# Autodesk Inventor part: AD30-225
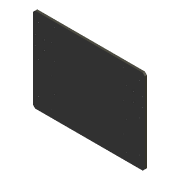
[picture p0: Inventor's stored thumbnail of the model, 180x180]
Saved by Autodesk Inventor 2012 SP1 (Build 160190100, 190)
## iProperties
Shininess: 0.0
Created: 2000-06
Part Number: AD30-225
Project: BONDING PRESS
Description: BASEPLATE, PRESS
Document SubType Name: Modeling
Designer: Ron
Material: Aluminum-6061
Density: 2.71 g/cm^3
Density: 0.0
Volumn: 0.0
Area: 0.0
PropertySet Name: Model Information
Control State: 0
Master: False
Checked Out: False
Title: BASEPLATE, PRESS
Author: Ron
Revision Number: A
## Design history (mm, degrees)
node "Extrusion1" dims "d2" = 12.7, "d3" = 0
  sketch "Sketch1"
    geometry: L1 (-330, 250)-(330, 250); L2 (330, 250)-(330, -250); L3 (330, -250)-(-330, -250); L4 (-330, -250)-(-330, 250); L5 (330, -250)-(-330, 250); 2 further points
    constraints: 10 end point, 2 parallel, 1 coincident, 1 horizontal, 1 midpoint, 1 perpendicular
    dimensions: "d0" = 660 distance of L1.start L1.end; "d1" = 500 distance of L1.end L2.end
node "Chamfer1" dims "d4" = 12.7, "d5" = 12.7, "d33" = 45 deg
node "Hole1" dims "d6" = 4.917, "d7" = 4, "d8" = 2, "d9" = 60 deg, "d10" = 8, "d11" = 118 deg, "d30" = 6
  sketch "Sketch2"
    geometry: L1 (-330, -237.3)-(-330, 237.3) reference; L2 (317.3, -250)-(-317.3, -250) reference; L3 (330, 237.3)-(330, -237.3) reference; L4 (-317.3, 250)-(317.3, 250) reference; L5 (0, 250)-(0, -250); L6 (-330, 0)-(330, 0); L7 (263.107, 127.188)-(317.082, 127.188); L8 (317.082, 127.188)-(317.082, 73.213); L9 (317.082, 73.213)-(263.107, 73.213); L10 (263.107, 73.213)-(263.107, 127.188); 6 further points
    constraints: 12 end point, 4 midpoint, 4 symmetric about line, 2 coincident, 2 parallel, 1 horizontal, 1 perpendicular
    dimensions: "d46" = 73.2125 distance from line of L8.end L6; "d47" = 127.1875 distance from line of point (317.082, 127.188) L6; "d48" = 263.10745 distance from line of L7.start L5; "d49" = 317.08245 distance from line of point (317.082, 127.188) L5
node "Hole2" dims "d12" = 3.242, "d13" = 4, "d14" = 2, "d15" = 60 deg, "d16" = 8, "d17" = 118 deg, "d31" = 6
  sketch "Sketch3"
    geometry: L1 (-330, -237.3)-(-330, 237.3) reference; L2 (317.3, -250)-(-317.3, -250) reference; L3 (330, 237.3)-(330, -237.3) reference; L4 (-317.3, 250)-(317.3, 250) reference; L5 (0, 250)-(0, -250); L6 (-330, 0)-(330, 0); 12 further points
    constraints: 6 symmetric about line, 4 end point, 4 midpoint, 4 vertical alignment
    dimensions: "d38" = 202.1 distance from line of L5 point (202.1, 220); "d39" = 220.1 distance from line of L5 point (220.1, 135); "d40" = 35 distance from line of point (220.1, -35) L6; "d41" = 120 distance from line of point (202.1, -120) L6; "d42" = 205 distance from line of point (220.1, -205) L6; "d43" = 50 distance from line of point (202.1, 50) L6; "d44" = 135 distance from line of point (220.1, 135) L6; "d45" = 220 distance from line of point (202.1, 220) L6
node "Hole3" dims "d18" = 4.2, "d19" = 8, "d20" = 4.5, "d21" = 60 deg, "d22" = 8, "d23" = 118 deg, "d50" = 6
  sketch "Sketch4"
    geometry: L1 (-330, -237.3)-(-330, 237.3) reference; L2 (317.3, -250)-(-317.3, -250) reference; L3 (-317.3, 250)-(317.3, 250) reference; L4 (0, 250)-(0, -250); L5 (0, 0)-(-330, 0); 1 further point
    constraints: 4 end point, 4 midpoint
    dimensions: "d34" = 298.25 distance from line of L4 point (-298.25, 200); "d51" = 200 distance from line of point (-298.25, 200) L5
pattern_linear "Rectangular Pattern1" dims "d54" = 190, "d57" = 596.5 (= 2 x d34)
body "Solid1"
